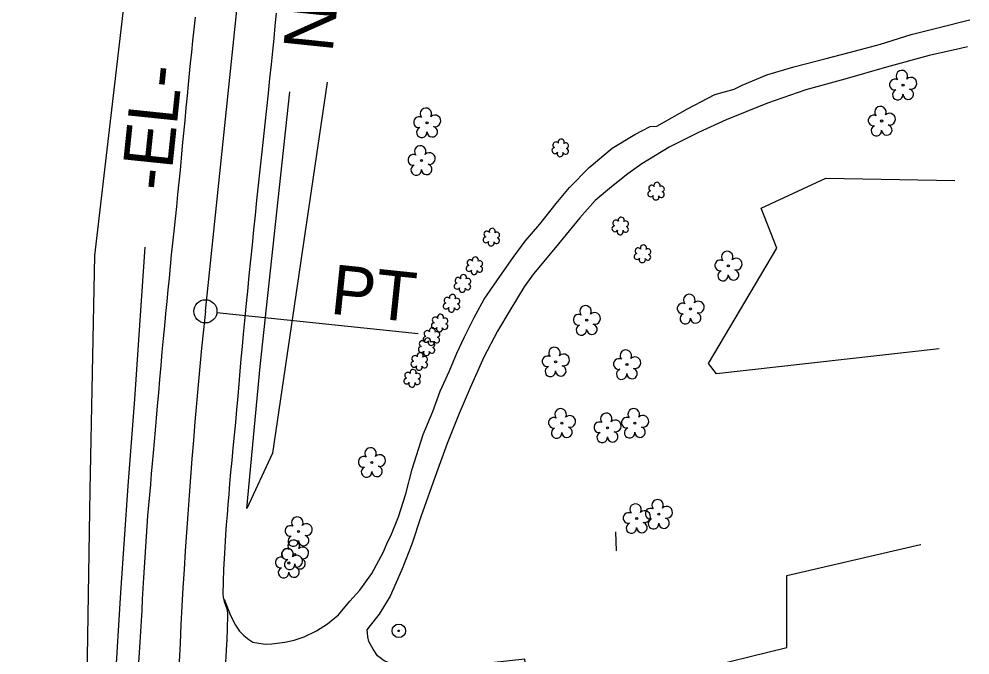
# Model space of a CAD drawing. Extents: x 473158 to 477500, y 500738 to 505114.
# Drawn here: x 474417.4 to 474724.5, y 503804.2 to 504009.5 of the extents above; entities that cross this region are included whole.
import ezdxf

# ---------------------------------------------------------------- set-up
doc = ezdxf.new("R2010")
doc.units = 0
for name, color, linetype in [('Exist Guardrail', 7, 'Continuous'), ('Exist Horizontal Alignment', 7, 'Continuous'), ('Exist Horizontal Alignment Direction Label', 7, 'Continuous'), ('Exist Other Culture Sign Post CELL', 7, 'Continuous'), ('Exist Roads EOP', 7, 'Continuous'), ('Exist Roads Soil', 7, 'Continuous'), ('Exist Structure Minor Culvert Topo', 7, 'Continuous'), ('Exist Vegetation Hedge Row', 7, 'Continuous'), ('Exist Vegetation Shrub CELL', 7, 'Continuous'), ('Exist Vegetation Tree CELL', 7, 'Continuous'), ('Exist Vegetation Woods Line', 7, 'Continuous')]:
    doc.layers.add(name, color=color, linetype=linetype)

msp = doc.modelspace()

# ---------------------------------------------------------------- linework, layer by layer
at = {"layer": 'Exist Guardrail'}
msp.add_lwpolyline([(474448.08, 503685.96), (474447.04, 503713.66), (474447.06, 503742.25), (474447.81, 503772.12), (474448.5, 503794.41), (474450.3, 503824.32), (474452.67, 503858.8), (474454.78, 503886.77), (474456.56, 503912.26), (474458.14, 503935.85)], dxfattribs=at)
at = {"layer": 'Exist Horizontal Alignment'}
for p, q in [((474477.6, 503915.15), (474513.31, 504258.14)), ((474481.33, 503914.76), (474546.27, 503908))]:
    msp.add_line(p, q, dxfattribs=at)
msp.add_circle((474477.6, 503915.15), 3.75, dxfattribs=at)
msp.add_arc((476415.56, 503713.38), 1948.44, 174.05611, 179.67611, dxfattribs=at)
at = {"layer": 'Exist Other Culture Sign Post CELL'}
for radius in [2.18, 0.24]:
    msp.add_circle((474540.07, 503811.98), radius, dxfattribs=at)
at = {"layer": 'Exist Roads EOP'}
for points in [[(474456.13, 503801.61), (474456.32, 503804.96), (474456.52, 503808.35), (474456.72, 503811.79), (474456.93, 503815.24), (474457.13, 503818.7), (474457.33, 503822.16), (474457.53, 503825.61), (474457.73, 503829.05), (474457.93, 503832.45), (474458.14, 503835.81), (474458.34, 503839.13), (474458.56, 503842.44), (474458.8, 503845.77), (474459.06, 503849.13), (474459.34, 503852.51), (474459.64, 503855.9), (474459.94, 503859.28), (474460.25, 503862.67), (474460.56, 503866.05), (474460.87, 503869.49), (474461.19, 503873.08), (474461.51, 503876.8), (474461.83, 503880.66), (474462.17, 503884.66), (474462.52, 503888.83), (474462.9, 503893.15), (474463.29, 503897.63), (474463.69, 503902.1), (474464.08, 503906.4), (474464.47, 503910.52), (474464.86, 503914.47), (474465.24, 503918.32), (474465.61, 503922.12), (474465.98, 503925.89), (474466.34, 503929.61), (474466.71, 503933.36), (474467.1, 503937.17), (474467.5, 503941.06), (474467.91, 503945.01), (474468.33, 503948.99), (474468.74, 503952.93), (474469.13, 503956.84), (474469.51, 503960.72), (474469.89, 503964.62), (474470.26, 503968.6), (474470.65, 503972.67), (474471.04, 503976.81), (474471.42, 503980.89), (474471.79, 503984.77), (474472.15, 503988.44), (474472.49, 503991.91), (474472.84, 503995.33), (474473.2, 503998.87), (474473.57, 504002.52), (474473.96, 504006.29), (474474.36, 504010.09)], [(474500.49, 504011.39), (474500.08, 504007.35), (474499.67, 504003.26), (474499.25, 503999.12), (474498.82, 503994.84), (474498.35, 503990.35), (474497.85, 503985.63), (474497.31, 503980.7), (474496.76, 503975.67), (474496.22, 503970.68), (474495.68, 503965.73), (474495.16, 503960.81), (474494.64, 503955.93), (474494.13, 503951.07), (474493.64, 503946.23), (474493.16, 503941.43), (474492.67, 503936.6), (474492.18, 503931.7), (474491.67, 503926.72), (474491.16, 503921.67), (474490.66, 503916.74), (474490.21, 503912.11), (474489.8, 503907.78), (474489.44, 503903.75), (474489.09, 503899.84), (474488.74, 503895.84), (474488.39, 503891.77), (474488.04, 503887.61), (474487.68, 503883.43), (474487.3, 503879.27), (474486.91, 503875.13), (474486.5, 503871.01), (474486.11, 503867), (474485.75, 503863.18), (474485.43, 503859.54), (474485.14, 503856.1), (474484.87, 503852.76), (474484.61, 503849.47), (474484.36, 503846.21), (474484.13, 503842.98), (474483.73, 503837), (474483.47, 503831.88), (474483.31, 503827.93), (474483.25, 503823.96), (474483.35, 503822.87), (474483.67, 503821.45), (474484.53, 503819.04), (474484.61, 503818.72), (474484.78, 503817.32), (474484.66, 503812.36), (474484.52, 503809.28), (474484.34, 503805.69), (474484.15, 503801.83)]]:
    msp.add_lwpolyline(points, dxfattribs=at)
at = {"layer": 'Exist Roads Soil'}
for points in [[(474483.65, 503822.23), (474485.74, 503816.95), (474487.38, 503813.76), (474488.65, 503811.9), (474490.04, 503810.48), (474491.64, 503809.18), (474492.92, 503808.34), (474494.91, 503807.97), (474496.89, 503807.68), (474499.11, 503807.74), (474503.31, 503808.32), (474506.31, 503808.98), (474509.52, 503810.06), (474513.44, 503812.03), (474517.05, 503814.27), (474520.54, 503817.09), (474524.27, 503821.59), (474527.44, 503825.11), (474531.39, 503830.5), (474535.09, 503837.54), (474536.44, 503840.56), (474537.45, 503842.7), (474539.92, 503848.79), (474542.29, 503856.24), (474544.39, 503864.15), (474547.96, 503875.37), (474551.09, 503882.84), (474553.47, 503889.35), (474556.41, 503895.94), (474558.84, 503901.64), (474561.27, 503906.9), (474564.42, 503913.13), (474567.69, 503919.13), (474572.75, 503926.39), (474576.98, 503932.48), (474580.84, 503937.79), (474585.63, 503943.35), (474590.92, 503949.97), (474595.22, 503955.09), (474601.56, 503961.61), (474608.97, 503967.82), (474616.33, 503972.28), (474621.29, 503974.8), (474623.46, 503974.97), (474633.26, 503980.55), (474642.16, 503985.22), (474648.39, 503986.87), (474650.92, 503988.14), (474658.93, 503991.48), (474667.61, 503994.12), (474678.11, 503996.75), (474687.55, 503999.23), (474695.64, 504001.47), (474705.5, 504004.59), (474715.85, 504007.08), (474723.1, 504008.95), (474724.55, 504009.31)], [(474723.72, 504000.51), (474721.49, 503999.97), (474711.31, 503997.78), (474697.55, 503994.04), (474684.14, 503990.16), (474671.5, 503986.64), (474659.2, 503982.4), (474645.79, 503977), (474636.87, 503972.91), (474627.44, 503968.18), (474618.55, 503962.76), (474614.04, 503959.55), (474608.76, 503955.34), (474603.53, 503950.91), (474598.58, 503945.33), (474590.67, 503935.74), (474583.52, 503927.25), (474580.58, 503923.09), (474575.88, 503915.42), (474571.99, 503908.71), (474567.56, 503900.38), (474563.09, 503890.42), (474559.6, 503882.21), (474555.7, 503872.49), (474552.22, 503862.98), (474547.23, 503848.81), (474544.25, 503839.91), (474541.16, 503832.02), (474537.27, 503823.19), (474533.71, 503817.4), (474530.39, 503813.13), (474529.8, 503812.44)], [(474517.99, 503800.68), (474519.38, 503800.1), (474521.04, 503799.45), (474523.44, 503798.14), (474529.1, 503795.95), (474533.69, 503793.96), (474539.74, 503793.01), (474549.11, 503793.58), (474560.58, 503795.23), (474573.42, 503796.48), (474581.44, 503797.23), (474580.76, 503802.78), (474569.86, 503801.64), (474559.4, 503800.51), (474553.46, 503800.27), (474546.75, 503799.92), (474541.65, 503800.24), (474537.98, 503801.17), (474535.29, 503802.27), (474533.22, 503803.9), (474531.77, 503806.01), (474530.44, 503808.57), (474530.1, 503810.09), (474529.8, 503812.44)]]:
    msp.add_lwpolyline(points, dxfattribs=at)
at = {"layer": 'Exist Structure Minor Culvert Topo'}
msp.add_line((474610.02, 503843.95), (474610.22, 503837.8), dxfattribs=at)
at = {"layer": 'Exist Vegetation Hedge Row'}
msp.add_lwpolyline([(474516.88, 503989.2), (474499.26, 503869.36), (474491.01, 503851.49), (474495.3, 503897.36), (474504.84, 503986.07)], dxfattribs=at)
at = {"layer": 'Exist Vegetation Shrub CELL'}
for p, q in [((474592.29, 503967.76), (474592.29, 503967.76)), ((474623.24, 503953.79), (474623.24, 503953.79)), ((474611.67, 503942.53), (474611.67, 503942.53)), ((474570.03, 503938.93), (474570.03, 503938.93)), ((474618.85, 503933.55), (474618.85, 503933.55)), ((474564.55, 503929.69), (474564.55, 503929.69)), ((474560.71, 503923.98), (474560.71, 503923.98)), ((474557.17, 503917.56), (474557.17, 503917.56)), ((474553.33, 503911.19), (474553.33, 503911.19)), ((474550.68, 503906.81), (474550.68, 503906.81)), ((474549.13, 503903.53), (474549.13, 503903.53)), ((474546.76, 503898.77), (474546.76, 503898.77)), ((474544.45, 503893.34), (474544.45, 503893.34))]:
    msp.add_line(p, q, dxfattribs=at)
for centre, radius, start, end in [((474590.81, 503968.88), 0.968, 35.8908, 245.4216), ((474592.52, 503969.8), 0.99, 334.8391, 200.4717), ((474590.49, 503967.05), 0.955, 95.1099, 327.9534), ((474592.16, 503966.07), 0.984, 151.2797, 21.387), ((474593.93, 503966.83), 0.937, 204.9913, 73.4601), ((474593.96, 503968.62), 0.929, 284.4567, 126.0861), ((474621.76, 503954.91), 0.968, 35.8908, 245.4216), ((474623.47, 503955.83), 0.99, 334.8391, 200.4717), ((474624.91, 503954.66), 0.929, 284.4567, 126.0861), ((474621.44, 503953.08), 0.955, 95.1099, 327.9534), ((474623.11, 503952.1), 0.984, 151.2797, 21.387), ((474624.88, 503952.86), 0.937, 204.9913, 73.4601), ((474611.9, 503944.57), 0.99, 334.8391, 200.4717), ((474570.25, 503940.97), 0.99, 334.8391, 200.4717), ((474609.87, 503941.83), 0.955, 95.1099, 327.9534), ((474610.18, 503943.66), 0.968, 35.8908, 245.4216), ((474613.3, 503941.61), 0.937, 204.9913, 73.4601), ((474613.34, 503943.4), 0.929, 284.4567, 126.0861), ((474568.23, 503938.23), 0.955, 95.1099, 327.9534), ((474568.54, 503940.06), 0.968, 35.8908, 245.4216), ((474571.66, 503938), 0.937, 204.9913, 73.4601), ((474571.7, 503939.8), 0.929, 284.4567, 126.0861), ((474611.54, 503940.85), 0.984, 151.2797, 21.387), ((474569.9, 503937.25), 0.984, 151.2797, 21.387), ((474619.08, 503935.59), 0.99, 334.8391, 200.4717), ((474564.78, 503931.73), 0.99, 334.8391, 200.4717), ((474617.05, 503932.85), 0.955, 95.1099, 327.9534), ((474617.37, 503934.68), 0.968, 35.8908, 245.4216), ((474620.49, 503932.62), 0.937, 204.9913, 73.4601), ((474620.52, 503934.42), 0.929, 284.4567, 126.0861), ((474562.75, 503928.98), 0.955, 95.1099, 327.9534), ((474563.07, 503930.82), 0.968, 35.8908, 245.4216), ((474566.19, 503928.76), 0.937, 204.9913, 73.4601), ((474566.22, 503930.56), 0.929, 284.4567, 126.0861), ((474618.72, 503931.87), 0.984, 151.2797, 21.387), ((474560.94, 503926.02), 0.99, 334.8391, 200.4717), ((474564.42, 503928), 0.984, 151.2797, 21.387), ((474558.91, 503923.28), 0.955, 95.1099, 327.9534), ((474559.23, 503925.11), 0.968, 35.8908, 245.4216), ((474562.35, 503923.05), 0.937, 204.9913, 73.4601), ((474562.38, 503924.85), 0.929, 284.4567, 126.0861), ((474557.4, 503919.61), 0.99, 334.8391, 200.4717), ((474560.58, 503922.3), 0.984, 151.2797, 21.387), ((474555.37, 503916.86), 0.955, 95.1099, 327.9534), ((474555.68, 503918.69), 0.968, 35.8908, 245.4216), ((474558.8, 503916.64), 0.937, 204.9913, 73.4601), ((474558.84, 503918.43), 0.929, 284.4567, 126.0861), ((474557.04, 503915.88), 0.984, 151.2797, 21.387), ((474551.53, 503910.48), 0.955, 95.1099, 327.9534), ((474551.85, 503912.31), 0.968, 35.8908, 245.4216), ((474553.56, 503913.23), 0.99, 334.8391, 200.4717), ((474555, 503912.06), 0.929, 284.4567, 126.0861), ((474549.19, 503907.94), 0.968, 35.8908, 245.4216), ((474550.9, 503908.85), 0.99, 334.8391, 200.4717), ((474552.35, 503907.68), 0.929, 284.4567, 126.0861), ((474553.2, 503909.5), 0.984, 151.2797, 21.387), ((474554.97, 503910.26), 0.937, 204.9913, 73.4601), ((474547.65, 503904.65), 0.968, 35.8908, 245.4216), ((474548.88, 503906.11), 0.955, 95.1099, 327.9534), ((474549.36, 503905.57), 0.99, 334.8391, 200.4717), ((474550.55, 503905.13), 0.984, 151.2797, 21.387), ((474550.8, 503904.4), 0.929, 284.4567, 126.0861), ((474552.31, 503905.88), 0.937, 204.9913, 73.4601), ((474547.33, 503902.82), 0.955, 95.1099, 327.9534), ((474549, 503901.84), 0.984, 151.2797, 21.387), ((474550.77, 503902.6), 0.937, 204.9913, 73.4601), ((474544.95, 503898.06), 0.955, 95.1099, 327.9534), ((474545.27, 503899.9), 0.968, 35.8908, 245.4216), ((474546.98, 503900.81), 0.99, 334.8391, 200.4717), ((474548.43, 503899.64), 0.929, 284.4567, 126.0861), ((474544.68, 503895.38), 0.99, 334.8391, 200.4717), ((474546.63, 503897.08), 0.984, 151.2797, 21.387), ((474548.39, 503897.84), 0.937, 204.9913, 73.4601), ((474542.65, 503892.64), 0.955, 95.1099, 327.9534), ((474542.96, 503894.47), 0.968, 35.8908, 245.4216), ((474546.08, 503892.41), 0.937, 204.9913, 73.4601), ((474546.12, 503894.21), 0.929, 284.4567, 126.0861), ((474544.32, 503891.66), 0.984, 151.2797, 21.387)]:
    msp.add_arc(centre, radius, start, end, dxfattribs=at)
at = {"layer": 'Exist Vegetation Tree CELL'}
for p, q in [((474702.92, 503988.2), (474702.92, 503988.2)), ((474549.19, 503976.05), (474549.19, 503976.05)), ((474696.02, 503976.61), (474696.02, 503976.61)), ((474547.39, 503963.89), (474547.39, 503963.89)), ((474646.51, 503929.82), (474646.51, 503929.82)), ((474634.28, 503915.91), (474634.28, 503915.91)), ((474600.75, 503912.27), (474600.75, 503912.27)), ((474590.73, 503898.84), (474590.73, 503898.84)), ((474613.76, 503897.97), (474613.76, 503897.97)), ((474592.73, 503879), (474592.73, 503879)), ((474607.45, 503877.54), (474607.45, 503877.54)), ((474616.33, 503879.04), (474616.33, 503879.04)), ((474531.33, 503866.37), (474531.33, 503866.37)), ((474616.9, 503848.25), (474616.9, 503848.25)), ((474624.03, 503849.65), (474624.03, 503849.65)), ((474507.68, 503844.05), (474507.68, 503844.05)), ((474506.52, 503836.57), (474506.52, 503836.57)), ((474504.54, 503833.88), (474504.54, 503833.88))]:
    msp.add_line(p, q, dxfattribs=at)
for centre in [(474702.92, 503988.2), (474549.19, 503976.05), (474696.02, 503976.61), (474547.39, 503963.89), (474646.51, 503929.82), (474634.28, 503915.91), (474600.75, 503912.27), (474590.73, 503898.84), (474613.76, 503897.97), (474592.73, 503879), (474607.45, 503877.54), (474616.33, 503879.04), (474531.33, 503866.37), (474624.03, 503849.65), (474616.9, 503848.25), (474507.68, 503844.05), (474506.52, 503836.57), (474504.54, 503833.88)]:
    msp.add_circle(centre, 0.326, dxfattribs=at)
for centre, radius, start, end in [((474702.53, 503991.08), 1.86, 330.1651, 219.7134), ((474700.31, 503988.36), 1.73, 62.6636, 279.3457), ((474705.47, 503988.79), 1.9, 257.1011, 134.1999), ((474701.22, 503985.08), 1.69, 111.5671, 6.231), ((474704.59, 503985.3), 1.7, 181.2822, 74.56), ((474548.81, 503978.92), 1.86, 330.1651, 219.7134), ((474695.63, 503979.49), 1.86, 330.1651, 219.7134), ((474698.56, 503977.2), 1.9, 257.1011, 134.1999), ((474546.59, 503976.2), 1.73, 62.6636, 279.3457), ((474551.74, 503976.64), 1.9, 257.1011, 134.1999), ((474693.41, 503976.77), 1.73, 62.6636, 279.3457), ((474547.49, 503972.93), 1.69, 111.5671, 6.231), ((474550.86, 503973.15), 1.7, 181.2822, 74.56), ((474694.31, 503973.49), 1.69, 111.5671, 6.231), ((474697.69, 503973.72), 1.7, 181.2822, 74.56), ((474547, 503966.77), 1.86, 330.1651, 219.7134), ((474544.78, 503964.05), 1.73, 62.6636, 279.3457), ((474549.94, 503964.48), 1.9, 257.1011, 134.1999), ((474545.68, 503960.77), 1.69, 111.5671, 6.231), ((474549.06, 503960.99), 1.7, 181.2822, 74.56), ((474646.12, 503932.69), 1.86, 330.1651, 219.7134), ((474643.9, 503929.97), 1.73, 62.6636, 279.3457), ((474649.05, 503930.41), 1.9, 257.1011, 134.1999), ((474644.8, 503926.7), 1.69, 111.5671, 6.231), ((474648.18, 503926.92), 1.7, 181.2822, 74.56), ((474633.9, 503918.79), 1.86, 330.1651, 219.7134), ((474631.68, 503916.07), 1.73, 62.6636, 279.3457), ((474636.83, 503916.5), 1.9, 257.1011, 134.1999), ((474600.37, 503915.14), 1.86, 330.1651, 219.7134), ((474603.3, 503912.86), 1.9, 257.1011, 134.1999), ((474632.58, 503912.79), 1.69, 111.5671, 6.231), ((474635.96, 503913.01), 1.7, 181.2822, 74.56), ((474598.15, 503912.42), 1.73, 62.6636, 279.3457), ((474599.05, 503909.15), 1.69, 111.5671, 6.231), ((474602.43, 503909.37), 1.7, 181.2822, 74.56), ((474590.34, 503901.72), 1.86, 330.1651, 219.7134), ((474613.38, 503900.84), 1.86, 330.1651, 219.7134), ((474588.12, 503899), 1.73, 62.6636, 279.3457), ((474593.27, 503899.43), 1.9, 257.1011, 134.1999), ((474611.15, 503898.12), 1.73, 62.6636, 279.3457), ((474616.31, 503898.55), 1.9, 257.1011, 134.1999), ((474589.02, 503895.72), 1.69, 111.5671, 6.231), ((474592.4, 503895.95), 1.7, 181.2822, 74.56), ((474612.06, 503894.85), 1.69, 111.5671, 6.231), ((474615.43, 503895.07), 1.7, 181.2822, 74.56), ((474592.34, 503881.87), 1.86, 330.1651, 219.7134), ((474615.94, 503881.91), 1.86, 330.1651, 219.7134), ((474590.12, 503879.15), 1.73, 62.6636, 279.3457), ((474595.28, 503879.58), 1.9, 257.1011, 134.1999), ((474607.07, 503880.42), 1.86, 330.1651, 219.7134), ((474613.72, 503879.19), 1.73, 62.6636, 279.3457), ((474618.88, 503879.63), 1.9, 257.1011, 134.1999), ((474591.02, 503875.87), 1.69, 111.5671, 6.231), ((474594.4, 503876.1), 1.7, 181.2822, 74.56), ((474604.85, 503877.7), 1.73, 62.6636, 279.3457), ((474610, 503878.13), 1.9, 257.1011, 134.1999), ((474614.62, 503875.92), 1.69, 111.5671, 6.231), ((474618, 503876.14), 1.7, 181.2822, 74.56), ((474605.75, 503874.42), 1.69, 111.5671, 6.231), ((474609.13, 503874.64), 1.7, 181.2822, 74.56), ((474528.73, 503866.52), 1.73, 62.6636, 279.3457), ((474530.95, 503869.24), 1.86, 330.1651, 219.7134), ((474533.88, 503866.96), 1.9, 257.1011, 134.1999), ((474529.63, 503863.25), 1.69, 111.5671, 6.231), ((474533.01, 503863.47), 1.7, 181.2822, 74.56), ((474616.51, 503851.12), 1.86, 330.1651, 219.7134), ((474623.65, 503852.53), 1.86, 330.1651, 219.7134), ((474614.29, 503848.4), 1.73, 62.6636, 279.3457), ((474619.45, 503848.84), 1.9, 257.1011, 134.1999), ((474621.43, 503849.81), 1.73, 62.6636, 279.3457), ((474626.58, 503850.24), 1.9, 257.1011, 134.1999), ((474507.29, 503846.93), 1.86, 330.1651, 219.7134), ((474618.57, 503845.35), 1.7, 181.2822, 74.56), ((474622.33, 503846.53), 1.69, 111.5671, 6.231), ((474625.71, 503846.76), 1.7, 181.2822, 74.56), ((474505.07, 503844.21), 1.73, 62.6636, 279.3457), ((474510.23, 503844.64), 1.9, 257.1011, 134.1999), ((474615.19, 503845.13), 1.69, 111.5671, 6.231), ((474506.13, 503839.44), 1.86, 330.1651, 219.7134), ((474505.97, 503840.93), 1.69, 111.5671, 6.231), ((474509.35, 503841.15), 1.7, 181.2822, 74.56), ((474503.91, 503836.72), 1.73, 62.6636, 279.3457), ((474504.15, 503836.76), 1.86, 330.1651, 219.7134), ((474509.06, 503837.15), 1.9, 257.1011, 134.1999), ((474501.93, 503834.04), 1.73, 62.6636, 279.3457), ((474504.81, 503833.45), 1.69, 111.5671, 6.231), ((474507.09, 503834.47), 1.9, 257.1011, 134.1999), ((474508.19, 503833.67), 1.7, 181.2822, 74.56), ((474502.83, 503830.76), 1.69, 111.5671, 6.231), ((474506.21, 503830.98), 1.7, 181.2822, 74.56)]:
    msp.add_arc(centre, radius, start, end, dxfattribs=at)
at = {"layer": 'Exist Vegetation Woods Line'}
for points in [[(474494.78, 504312.62), (474476.79, 504178.44), (474459.77, 504087.31), (474441.83, 503933.16), (474440.33, 503857.37), (474437.89, 503709.04), (474417.41, 503659.72)], [(474714.57, 503903.05), (474642.64, 503894.94), (474640.09, 503898.28), (474662.15, 503935.57), (474657.1, 503948.43), (474678.02, 503958.1), (474719.67, 503957.37)], [(474635.55, 503799.27), (474665.43, 503806.64), (474665.4, 503829.84), (474708.52, 503839.82), (474708.64, 503839.85)]]:
    msp.add_lwpolyline(points, dxfattribs=at)

# ---------------------------------------------------------------- texts
at = {"layer": 'Exist Horizontal Alignment'}
msp.add_text('PT', height=16, rotation=354.0561, dxfattribs=at).set_placement((474517.6, 503914.43))
at = {"layer": 'Exist Horizontal Alignment Direction Label'}
for s, p in [('N 5%%d 56\' 38" E', (474518.64, 503998.48)), ('-EL-', (474466.14, 503953.73))]:
    msp.add_text(s, height=16, rotation=84.0561, dxfattribs=at).set_placement(p)

doc.saveas('drawing.dxf')
